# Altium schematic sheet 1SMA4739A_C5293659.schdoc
size 127 x 101 mm
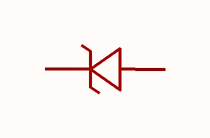
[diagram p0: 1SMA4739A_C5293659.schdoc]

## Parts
D?  1sma4739a_c5293659  [SMAG_L4.3-W2.6-LS5.3-RD]  (value not drawn)

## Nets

Not connected (* = marked no-connect by the designer): D? 1(K) 2(A)

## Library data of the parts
D? = 1sma4739a_c5293659: 二极管配置:1个独立式;稳压值(标称值):9.1V;稳压值(范围值):-;耗散功率(Pd):1W;; Manufacturer: CJ(江苏长电/长晶); AddInBom: yes; ModelId: 3cd8680d946b497db8ea5837610a9736; ModelTransform: 208.661,102.362,0,0,0,0,0,0,0; Diode Configuration: 1个独立式; Zener Voltage(Nom): 9.1V; Reverse Leakage Current (Ir): 500nA@7V; Pd - Power Dissipation: 1W; Impedance(Zzt): 5Ω; Impedance(Zzk): 700Ω; Operating Junction Temperature Range: -55℃~+150℃; Tolerance: ±5%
